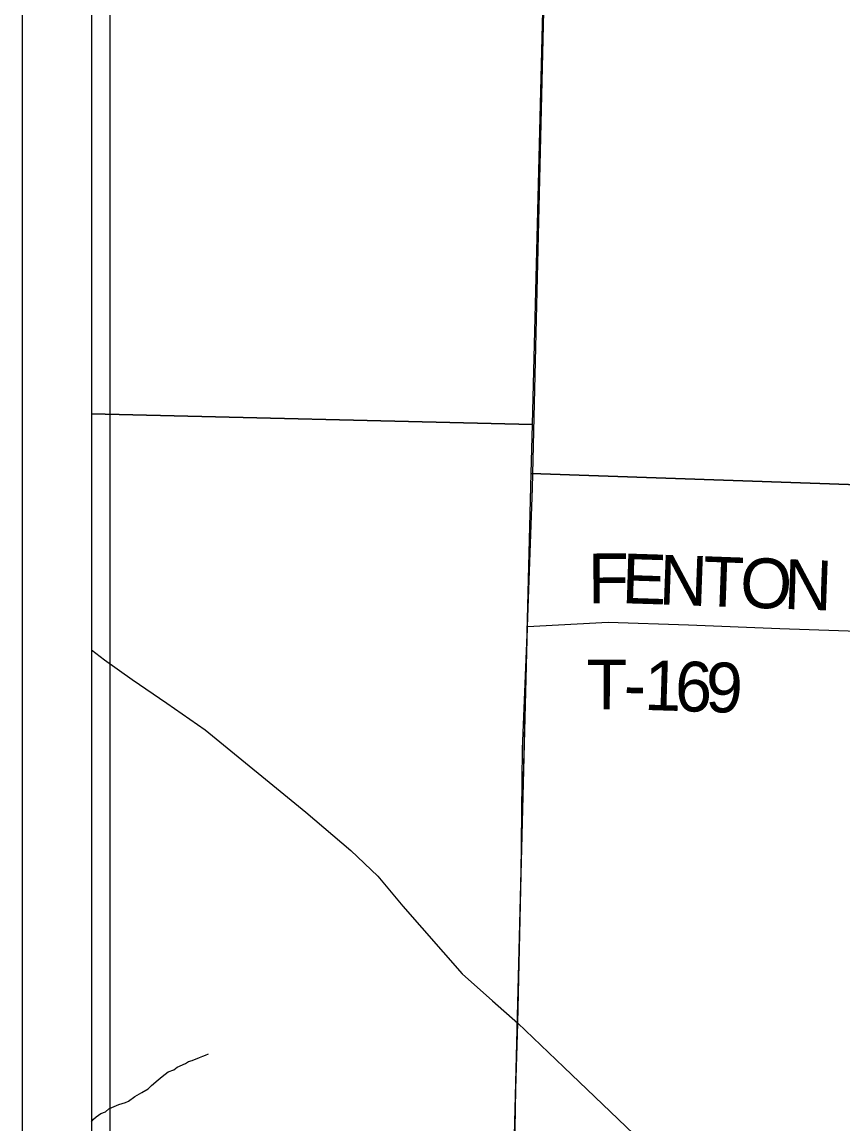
# Model space of a CAD drawing. Extents: x 0 to 34, y -2.3 to 22.
# Drawn here: x 2 to 2.936, y 18.694 to 19.952 of the extents above; entities that cross this region are included whole.
import ezdxf

# ---------------------------------------------------------------- set-up
doc = ezdxf.new("R2010")
doc.units = 0
for name, color, linetype in [('GM_X_County', 7, 'Continuous'), ('GM_X_County_Road', 7, 'Continuous'), ('GM_X_Minor_River', 7, 'Continuous'), ('GM_X_Section', 7, 'Continuous'), ('GM_X_Township', 7, 'Continuous'), ('GM_X_Township_Road', 7, 'Continuous'), ('GM_X_Township_Road_Text', 7, 'Continuous'), ('SH_Data', 7, 'Continuous')]:
    doc.layers.add(name, color=color, linetype=linetype)

msp = doc.modelspace()

# ---------------------------------------------------------------- linework, layer by layer
at = {"layer": 'GM_X_County'}
msp.add_line((2.0792, 20.8994), (2.0792, 14.4971), dxfattribs=at)
at = {"layer": 'GM_X_County_Road'}
for p, q in [((2.0792, 19.2355), (2.094, 19.2241)), ((2.094, 19.2241), (2.1257, 19.2014)), ((2.1257, 19.2014), (2.165, 19.1746)), ((2.165, 19.1746), (2.209, 19.1441)), ((2.209, 19.1441), (2.3238, 19.0503)), ((2.3238, 19.0503), (2.3752, 19.0066)), ((2.3752, 19.0066), (2.406, 18.9774)), ((2.406, 18.9774), (2.4344, 18.943)), ((2.4344, 18.943), (2.502, 18.8657)), ((2.502, 18.8657), (2.5367, 18.8349)), ((2.5367, 18.8349), (2.5657, 18.8095)), ((2.5657, 18.8095), (2.6179, 18.7592)), ((2.6179, 18.7592), (2.7534, 18.6302))]:
    msp.add_line(p, q, dxfattribs=at)
at = {"layer": 'GM_X_Minor_River'}
for p, q in [((2.1942, 18.767), (2.2023, 18.7702)), ((2.2023, 18.7702), (2.2061, 18.772)), ((2.2061, 18.772), (2.2092, 18.773)), ((2.2092, 18.773), (2.2127, 18.7744)), ((2.173, 18.7562), (2.1769, 18.7592)), ((2.1769, 18.7592), (2.1865, 18.7634)), ((2.1865, 18.7634), (2.19, 18.7656)), ((2.19, 18.7656), (2.1942, 18.767)), ((2.1478, 18.7384), (2.1552, 18.745)), ((2.1552, 18.745), (2.1598, 18.7487)), ((2.1598, 18.7487), (2.1668, 18.7538)), ((2.1668, 18.7538), (2.173, 18.7562)), ((2.1365, 18.7304), (2.1438, 18.7347)), ((2.1438, 18.7347), (2.1478, 18.7384)), ((2.1179, 18.7188), (2.1214, 18.7206)), ((2.1214, 18.7206), (2.1288, 18.7257)), ((2.1288, 18.7257), (2.1365, 18.7304)), ((2.0898, 18.7063), (2.0952, 18.7084)), ((2.0952, 18.7084), (2.0991, 18.7117)), ((2.0991, 18.7117), (2.1025, 18.7132)), ((2.1025, 18.7132), (2.1103, 18.7167)), ((2.1103, 18.7167), (2.1179, 18.7188)), ((2.0792, 18.697), (2.0816, 18.7001)), ((2.0816, 18.7001), (2.0844, 18.7027)), ((2.0844, 18.7027), (2.0898, 18.7063))]:
    msp.add_line(p, q, dxfattribs=at)
at = {"layer": 'GM_X_Section'}
for p, q in [((2.0792, 20.467), (2.0792, 19.5047)), ((2.5825, 19.4927), (2.6062, 20.454)), ((2.5825, 19.4927), (2.6062, 20.454)), ((2.0792, 19.5047), (2.0792, 18.5025)), ((2.0792, 19.5047), (2.5825, 19.4927)), ((2.5825, 19.4927), (2.0792, 19.5047)), ((2.5808, 19.4367), (2.5825, 19.4927)), ((2.5808, 19.4367), (2.5825, 19.4927)), ((2.5569, 18.4898), (2.5808, 19.4367)), ((2.5569, 18.4898), (2.5808, 19.4367)), ((3.5861, 19.4021), (2.5808, 19.4367)), ((2.5808, 19.4367), (3.5861, 19.4021))]:
    msp.add_line(p, q, dxfattribs=at)
at = {"layer": 'GM_X_Township'}
for p, q in [((2.0792, 20.467), (2.0792, 14.4971)), ((2.5838, 19.485), (2.5976, 20.0643)), ((2.5838, 19.485), (2.5976, 20.0643)), ((2.5823, 19.42), (2.5838, 19.485)), ((2.5823, 19.42), (2.5838, 19.485)), ((2.5767, 19.262), (2.5823, 19.42)), ((2.5767, 19.262), (2.5823, 19.42)), ((2.5695, 18.9793), (2.5767, 19.262)), ((2.5695, 18.9793), (2.5767, 19.262)), ((2.5657, 18.8095), (2.5695, 18.9793)), ((2.5657, 18.8095), (2.5695, 18.9793)), ((2.5635, 18.7342), (2.5657, 18.8095)), ((2.5635, 18.7342), (2.5657, 18.8095)), ((2.5615, 18.6201), (2.5635, 18.7342)), ((2.5615, 18.6201), (2.5635, 18.7342))]:
    msp.add_line(p, q, dxfattribs=at)
at = {"layer": 'GM_X_Township_Road'}
for p, q in [((2.5838, 19.485), (2.5976, 20.0643)), ((2.5823, 19.42), (2.5838, 19.485)), ((2.5767, 19.262), (2.5823, 19.42)), ((2.5709, 19.122), (2.5767, 19.262)), ((2.5767, 19.262), (2.6688, 19.267)), ((2.6688, 19.267), (2.7602, 19.2639)), ((2.7602, 19.2639), (2.8646, 19.2598)), ((2.8646, 19.2598), (3.0318, 19.2541)), ((2.5695, 18.9793), (2.5709, 19.122)), ((2.5657, 18.8095), (2.5695, 18.9793)), ((2.5635, 18.7342), (2.5657, 18.8095)), ((2.5615, 18.6201), (2.5635, 18.7342))]:
    msp.add_line(p, q, dxfattribs=at)
at = {"layer": 'SH_Data'}
for p, q in [((2, 21), (2, 14)), ((2.1, 20.9), (2.1, 14.1))]:
    msp.add_line(p, q, dxfattribs=at)

# ---------------------------------------------------------------- texts
at = {"layer": 'GM_X_Township_Road_Text'}
for s, rotation, p in [('F', 0.2471, (2.6458, 19.2885)), ('E', 358.1633, (2.6836, 19.2887)), ('N', 357.9359, (2.726, 19.2873)), ('T', 357.9339, (2.7759, 19.2855)), ('O', 357.9339, (2.8184, 19.284)), ('N', 357.9341, (2.8684, 19.2822)), ('T', 359.8393, (2.6438, 19.1676)), ('1', 358.2694, (2.7092, 19.1669)), ('6', 358.1575, (2.7442, 19.1658)), ('9', 358.1263, (2.7791, 19.1647)), ('-', 358.5714, (2.686, 19.1675))]:
    msp.add_text(s, height=0.0568, rotation=rotation, dxfattribs=at).set_placement(p)

doc.saveas('drawing.dxf')
